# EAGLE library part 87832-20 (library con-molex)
Milli-Grid Header 2.00mm (.079") Pitch
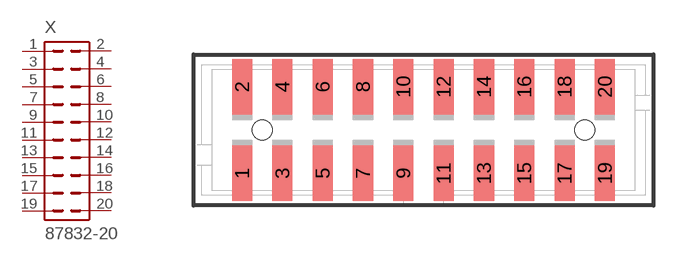
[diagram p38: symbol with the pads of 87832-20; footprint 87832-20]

Designator prefix X

## 87832-20 (OC_FARNELL: unknown; OC_NEWARK: unknown)  [87832-20]
1  1  pas
2  2  pas
3  3  pas
4  4  pas
5  5  pas
6  6  pas
7  7  pas
8  8  pas
9  9  pas
10  10  pas
11  11  pas
12  12  pas
13  13  pas
14  14  pas
15  15  pas
16  16  pas
17  17  pas
18  18  pas
19  19  pas
20  20  pas

## Footprint 87832-20 (pad centres in mm)
PCB Headers 2.00mm (.079") Pitch Milli-Grid Header, Vertical, Shrouded
smd 1 x 2.75: 1 -9,-2.15; 2 -9,2.15; 3 -7,-2.15; 4 -7,2.15; 5 -5,-2.15; 6 -5,2.15; 7 -3,-2.15; 8 -3,2.15; 9 -1,-2.15; 10 -1,2.15; 11 1,-2.15; 12 1,2.15; 13 3,-2.15; 14 3,2.15; 15 5,-2.15; 16 5,2.15; 17 7,-2.15; 18 7,2.15; 19 9,-2.15; 20 9,2.15
hole 1 at -8,0
hole 1 at 8,0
